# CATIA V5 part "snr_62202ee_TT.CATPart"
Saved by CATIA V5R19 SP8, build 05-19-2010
Part number: snr_62202ee_1_1.1
Nomenclature: 39_b
Source: Unknown
Description: PART-snr_62202ee_1_1-DESC
Bounding box of the stored display mesh (mm): x 0 to 14, y -17.5 to 17.5, z -17.5 to 17.5
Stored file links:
  C:\Users\rphgr\Desktop\0_Tapis_TC520B_vitesse\snr_62202ee_TT.CATPart
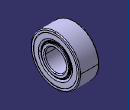
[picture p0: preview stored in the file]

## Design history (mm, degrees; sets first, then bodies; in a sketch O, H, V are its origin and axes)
AxisSystem1: origin (0, 0, 0), X (1, 0, 0), Y (0, 1, 0), Z (0, 0, 1)
Body1 "snr_62202ee_1_1" (main body)
  Solid1: solid without history
Body2 "snr_62202ee_1_2"
  Solid2: solid without history
Body3 "snr_62202ee_1_3"
  Solid3: solid without history
Body4 "snr_62202ee_1_4"
  Solid4: solid without history
Body5 "snr_62202ee_1_5"
  Solid5: solid without history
